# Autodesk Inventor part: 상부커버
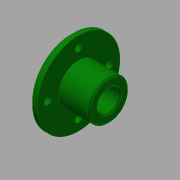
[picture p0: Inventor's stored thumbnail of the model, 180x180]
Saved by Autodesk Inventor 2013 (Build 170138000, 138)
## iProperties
Created: 2015-09
Part Number: 상부커버
Material: 알루미늄 6061
Document SubType Name: Modeling
Designer: mduedu
Density: 1 g/cm^3
Author: mduedu
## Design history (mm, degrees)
sketch "스케치1"
  geometry: L1 (-12.5, 0)-(12.5, 0); L2 (-12.5, 0)-(-12.5, 27); L3 (-12.5, 27)-(-7.5, 27); L4 (-7.5, 27)-(-7.5, 13); L5 (-7.5, 13)-(12.5, 13); L6 (12.5, 13)-(12.5, 0); 2 further points
  constraints: 12 end point, 2 parallel, 2 perpendicular, 1 coincident, 1 horizontal, 1 midpoint, 1 vertical
  dimensions: "d0" = 25 distance of L1.start L1.end; "d2" = 5 distance of L2.end L3.end; "d3" = 26 diameter of L5 L1; "d4" = 54 diameter of L3 L1
revolve "회전1" sketch "스케치1" stored, may be unused: angle "d5" = 90 deg
hole "구멍1" diameter "d8" = 14; stored, may be unused: countersink angle "d12" = 90 deg, drill point angle "d14" = 118 deg; dims "d6" = 10, "d7" = 10, "d9" = 6, "d10" = 4, "d11" = 2, "d13" = 8
chamfer "모따기1" distance "d15" = 1; stored, may be unused: second distance "d16" = 2, angle "d17" = 45 deg
chamfer "모따기2" distance "d18" = 2; stored, may be unused: second distance "d19" = 2, angle "d20" = 45 deg
sketch "스케치2" dims "d21" = 40
  geometry: 6 further points
  constraints: 2 vertical alignment, 1 coincident, 7 other
  dimensions: "d25" = 360 deg dimension on point (0, 0) point (0, 20) (derived)
sketch "스케치3"
  geometry: 4 further points
hole "구멍2" sketch "스케치3" at (0, 20), (-20, 0), (20, 0), (0, -20) diameter "d27" = 4.5; stored, may be unused: countersink angle "d31" = 90 deg, drill point angle "d33" = 0 deg; dims "d28" = 6, "d29" = 4, "d30" = 2, "d32" = 8
chamfer "모따기3" distance "d34" = 1; stored, may be unused: second distance "d35" = 2, angle "d36" = 45 deg
node "솔리드1"
